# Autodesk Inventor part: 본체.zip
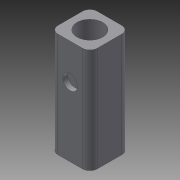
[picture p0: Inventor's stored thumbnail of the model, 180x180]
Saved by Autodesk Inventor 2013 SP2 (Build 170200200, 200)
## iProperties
Created: 2024-07
Part Number: 본체.zip
Material: Generic
Document SubType Name: Modeling
Designer: a
Density: 1 g/cm^3
Author: a
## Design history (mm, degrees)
sketch "스케치1"
  geometry: L1 (-25, 40)-(25, 40); L2 (40, 25)-(40, -25); L3 (25, -40)-(-25, -40); L4 (-40, -25)-(-40, 25); L5 (-40, 40)-(40, -40); L6 (40, 40)-(-40, -40); A1 r 15 centre (-25, 25) between (-25, 40) and (-40, 25); A2 r 15 centre (25, 25) between (40, 25) and (25, 40); A3 r 15 centre (-25, -25) between (-40, -25) and (-25, -40); A4 r 15 centre (25, -25) between (25, -40) and (40, -25); 1 further point
  constraints: 12 end point, 8 point on circle, 8 point on line, 8 tangent, 4 centre point, 3 equal radius, 2 midpoint, 2 parallel, 1 horizontal, 1 perpendicular
  dimensions: "d0" = 80 distance of L5.start L6.start; "d2" = 80 distance of L6.start L5.end; "d3" = 15 radius of A1
extrude "돌출1" new body sketch "스케치1" stored distance "d4" = 212; taper "d5" = 0 deg
sketch "스케치2"
  geometry: L1 (0, 212)-(50, 212) reference; 2 further points
  constraints: 1 vertical alignment, 1 other
  dimensions: "d6" = 90 distance from line of L1 point (25, 122)
feature "엠보싱1" sketch "스케치2" dims "d2" = 80, "d7" = 0.5, "d8" = 0
sketch "스케치3"
  geometry: C1 r 20.5 at (0, 0); 1 further point
  constraints: 1 centre point, 1 coincident
  dimensions: "d9" = 41 diameter of C1
extrude "돌출2" cut sketch "스케치3" distance "d11" = 2; taper "d12" = 0 deg
sketch "스케치4"
  geometry: C1 r 32 at (0, 0); 5 further points
  constraints: 1 centre point, 1 coincident, 1 vertical alignment, 5 other
  dimensions: "d13" = 64 diameter of C1; "d15" = 31.5 distance of point (0, 0) point (0, 31.5); "d18" = 360 deg dimension on C1.centre point (0, 31.5) (derived)
hole "구멍1" sketch "스케치4" at (0, 31.5), (-31.5, 0), (0, -31.5), (31.5, 0) diameter "d20" = 3.242; stored, may be unused: countersink angle "d24" = 82 deg, drill point angle "d26" = 118 deg; dims "d21" = 12, "d22" = 3.023, "d23" = 2, "d25" = 14
sketch "스케치5"
  geometry: C1 r 26 at (0, 0); 1 further point
  constraints: 1 centre point, 1 coincident
  dimensions: "d27" = 52 diameter of C1
extrude "돌출3" cut sketch "스케치5" distance "d29" = 217; taper "d30" = 0 deg
sketch "스케치6"
  geometry: C1 r 15 at (25, -71.932); 1 further point
  constraints: 1 centre point
  dimensions: "d31" = 30 diameter of C1
extrude "돌출4" cut sketch "스케치6" distance "d33" = 10; taper "d34" = 0 deg
node "솔리드1"
